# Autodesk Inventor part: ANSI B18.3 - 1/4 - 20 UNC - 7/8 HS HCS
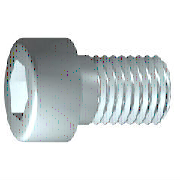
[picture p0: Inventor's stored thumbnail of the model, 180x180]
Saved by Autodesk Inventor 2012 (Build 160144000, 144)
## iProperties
IsCustomPart: 0
Created: 2008-01
Part Number: ANSI B18.3 - 1/4 - 20 UNC - 7/8 HS HCS
Material: Steel, Mild
Description: Hexagon Socket Head Cap Screw
Document SubType Name: Modeling
Standard: ANSI B18.3
Designer: latalom
Standard Revision: 2003
Standards Organization: ANSI
Language: en-US
Size Designation: 1/4 - 20 UNC - 7/8
Categories: <MemberInstance><Categories><Category DisplayName="Fasteners" InternalName="e4da775c-781d-43d5-af7c-5136215cf5a6" Mnemonic="FSTN"><Category DisplayName="Bolts"
Density: 7.86 g/cm^3
Mass: 8.45886 g
Surface Area: 8.12272 cm^2
Volume: 1.07619 cm^3
Author: latalom
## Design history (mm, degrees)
body "Solid1"
workplane "Work Plane1"
fillet "Fillet2" dims "d30" = 0.1778 (= R)
revolve "Body" stored, may be unused: angle "d10" = 90 deg
sketch "Sketch2"
  geometry: L1 (0, -6.668)-(0, 6.668) reference; L2 (-6.668, 0)-(6.668, 0) reference; L3 (2.757, 0)-(1.378, -2.388); L4 (1.378, -2.388)-(-1.378, -2.388); L5 (-1.378, -2.388)-(-2.757, 0); L6 (-2.757, 0)-(-1.378, 2.388); L7 (-1.378, 2.388)-(1.378, 2.388); L8 (1.378, 2.388)-(2.757, 0); 2 further points
  constraints: 12 end point, 1 coincident, 1 horizontal alignment, 1 point on line, 12 other
extrude "Slot" join sketch "Sketch2" stored distance "d11" = 10; taper "d12" = 0 deg
fillet "Fillet1" dims "d17" = 0.635 (= RR)
feature "Thread" dims "d13" = 19.0498 (= GEL), "d14" = 0
chamfer "Chamfer1" distance "d15" = 0.75565 (= -0.5 x SPD + 0.5 x GD); stored, may be unused: second distance "d16" = 0.75565 (= GUL), angle "d27" = 45 deg
sketch "Sketch1"
  geometry: L1 (-1.71, 0)-(22.225, 0); L2 (22.225, 0)-(22.225, 3.175); L3 (22.225, 3.175)-(3.175, 3.175); L4 (3.175, 3.175)-(0, 3.175); L5 (0, 3.175)-(0, 3.175); L6 (0, 3.175)-(0, 4.763); L7 (0, 4.763)-(-6.35, 4.763); L8 (-6.35, 4.763)-(-6.35, 2.757); L9 (-6.35, 2.757)-(-3.302, 2.757); L10 (-3.302, 2.757)-(-1.71, 0); L11 (-12.065, 0)-(27.94, 0) reference; L12 (0, -0.953)-(0, 5.715) reference; L13 (3.175, 3.175)-(0, 3.175)
  constraints: 22 end point, 6 parallel, 2 collinear, 2 perpendicular, 1 horizontal, 1 point on line
  dimensions: "d1" = 19.0498 distance from line of L3.end L2 (= GEL); "d2" = 3.1751 distance of L4.end L3.end (computed from GAL); "d3" = 6.35 distance between parallel lines of L8 L6 (= KOH); "d4" = 3.048 distance of L8.end L9.end (= INTI); "d5" = 60 deg angle of L10 L1; "d6" = 6.35 diameter of L3 L1 (= GD); "d7" = 6.35 diameter of L5 L1 (= BDM); "d8" = 5.51393 diameter of L9 L1 (= 1.1547 x SW); "d9" = 9.525 diameter of L7 L1 (= KOD); "d26" = 22.225 distance between parallel lines of L12 L2 (= NLG)
other parameters: "GD" = 6.35 (= KOH) [user parameter; used in 2 equation terms], "NLG" = 22.225 [user parameter; used in 1 equation term], "GEL" = 19.0498 [user parameter; used in 2 equation terms], "KOD" = 9.525 [user parameter; used in 1 equation term], "KOH" = 6.35 [user parameter; used in 3 equation terms], "INTI" = 3.048 [user parameter; used in 1 equation term], "GAL" = 3.175 [user parameter; used in 1 equation term], "GUL" = 0.75565 [user parameter; used in 1 equation term], "BDM" = 6.35 (= KOH) [user parameter; used in 1 equation term], "SW" = 4.7752 [user parameter; used in 2 equation terms], "RR" = 0.635 [user parameter; used in 1 equation term], "SPD" = 4.8387 [user parameter; used in 2 equation terms], "d19" = 0, "d28" = 0, "d29" = 0, "R" = 0.1778 [user parameter; used in 1 equation term], "PHH" = 0.2032 [user parameter], "GD1" = 4.8387 (= SPD) [user parameter], "THREADDIA" = 6.35 [user parameter], "FAWI" = 45 deg [user parameter], "PTC" = 1.27 (computed from TPU) [user parameter], "KOH1" = 5.715 [user parameter], "NND" = 6.35 [user parameter], "TOA" = 30 deg [user parameter], "E0" = 5.51536 (= 1.155 x SW) [user parameter]
